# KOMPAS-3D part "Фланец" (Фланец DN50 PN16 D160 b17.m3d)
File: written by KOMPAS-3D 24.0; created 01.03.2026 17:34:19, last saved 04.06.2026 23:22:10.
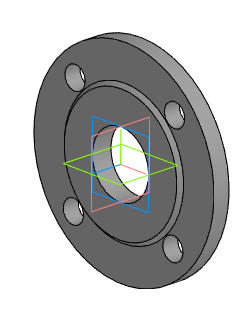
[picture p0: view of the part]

Document properties: Автор: R2D2; Полное имя файла: E:\Работа\Зайцев\GVWR3535M-2W-F-ОСТ Задвижка клиновая 30нж941нж DN.ru Ду50-200 Ру16\исходные данные\DN50\Фланец DN50 PN16 D160 b17.m3d

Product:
- Part/product: Фланец
    Масса: 1.899079
    additional columns: Типовые
- Part/product: Фланец  | designation 01
    Масса: 2.041312
    additional columns: Типовые

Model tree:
1. Эскиз:2
2. Элемент вращения:1
     Угол 1 = 360
3. Эскиз:3  (with: Грань.Элемент вращения:1)
4. Элемент выдавливания:2
     Расстояние 2 = 13
5. Массив по концентрической сетке:1  (with: Элемент выдавливания:2, Эскиз:3, Грань.Элемент вращения:1)  (4 pattern instances)
     Шаг 2 = 360

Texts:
  Линейный размер с обрывом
